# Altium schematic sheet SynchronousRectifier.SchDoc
size A; SheetNumber: 1; SheetTotal: 1
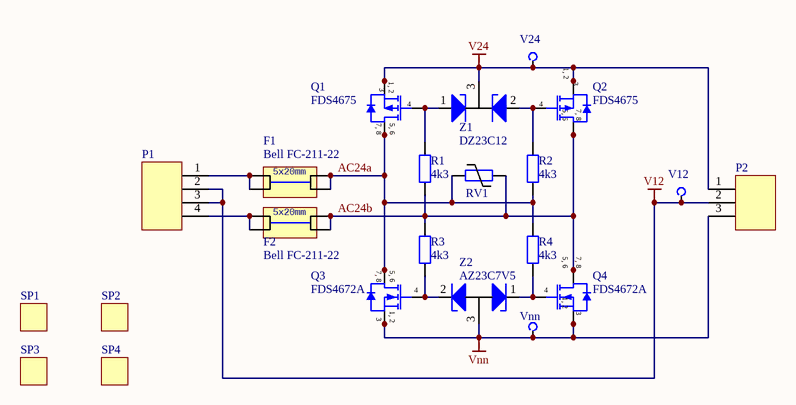
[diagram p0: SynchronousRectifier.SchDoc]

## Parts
F1  Bell FC-211-22  [FUSE_CLIP_5x20]
F2  Bell FC-211-22  [FUSE_CLIP_5x20]
P1  Terminal4_5.08mm  [MOLEX-39544-3004]  (value not drawn)
P2  Terminal3_5.08mm  [MOLEX-39544-3003]  (value not drawn)
Q1  FDS4675  [SO-8_M]
Q2  FDS4675  [SO-8_M]
Q3  FDS4672A  [SO-8_M]
Q4  FDS4672A  [SO-8_M]
R1  4k3  [CR1608-0603_N]
R2  4k3  [CR1608-0603_N]
R3  4k3  [CR1608-0603_N]
R4  4k3  [CR1608-0603_N]
RV1  V33MLA1206NHAUTO  [VR3216-1206]  (value not drawn)
SP1  Spacer-3mm-tapped x 10mm  [Spacer-3mm tapped x 10 mm]  (value not drawn)
SP2  Spacer-3mm-tapped x 10mm  [Spacer-3mm tapped x 10 mm]  (value not drawn)
SP3  Spacer-3mm-tapped x 10mm  [Spacer-3mm tapped x 10 mm]  (value not drawn)
SP4  Spacer-3mm-tapped x 10mm  [Spacer-3mm tapped x 10 mm]  (value not drawn)
V12  Power 12V FWR  [PCBPIN - 0.7mm]  (value not drawn)  (no BOM)
V24  Power 24V FWR  [PCBPIN - 0.7mm]  (value not drawn)  (no BOM)
Vnn  Power Ground  [PCBPIN - 0.7mm]  (value not drawn)  (no BOM)
Z1  DZ23C12  [SOT23_M]
Z2  AZ23C7V5  [SOT23_M]

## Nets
V12: P1.2 P1.3 P2.2 V12.1(TP)
V24: P2.1 Q1.1(S) Q1.2(S) Q1.3(S) Q2.1(S) Q2.2(S) Q2.3(S) V24.1(TP) Z1.3(K)
Vnn: P2.3 Q3.1(S) Q3.2(S) Q3.3(S) Q4.1(S) Q4.2(S) Q4.3(S) Vnn.1(TP) Z2.3(K)
AC24a: F1.2 F1.2a Q1.5(D) Q1.6(D) Q1.7(D) Q1.8(D) Q3.5(D) Q3.6(D) Q3.7(D) Q3.8(D) R2.1 R4.2 RV1.2
AC24b: F2.2 F2.2a Q2.5(D) Q2.6(D) Q2.7(D) Q2.8(D) Q4.5(D) Q4.6(D) Q4.7(D) Q4.8(D) R1.1 R3.2 RV1.1
NetF1_1: F1.1 F1.1a P1.1
NetF2_1: F2.1 F2.1a P1.4
NetQ1_4: Q1.4(G) R1.2 Z1.1(A1)
NetQ2_4: Q2.4(G) R2.2 Z1.2(A2)
NetQ3_4: Q3.4(G) R3.1 Z2.2(A2)
NetQ4_4: Q4.4(G) R4.1 Z2.1(A1)

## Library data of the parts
F1 F2 = FUSE_CLIP_5x20: 5x20mm fuse clip PCB Mount; Value: 10 A
P1 = Terminal4_5.08mm: MULTICOMP MC24368 TERMINAL BLOCK EUROSTYLE, 4 POSITION, 26-12AWG, 5.08mm
P2 = Terminal3_5.08mm: MULTICOMP MC24367 TERMINAL BLOCK EUROSTYLE, 3 POSITION, 26-12AWG, 5.08mm
Q1 Q2 = FDS4675: P-Channel Power MOSFET, 11 A, 40 V, RDS(ON) = 0.013 ohm @ VGS = -10   VRDS(ON) = 0.017 ohm @ VGS =   -4.5 VC; Manufacturer: Fairchild Semiconductor; Package Version: Rev. 16, 08/2015; Qg Gate Charge: 56nC; Drain-to-Source Voltage [Vdss]: 40V; Drain-Source On Resistance-Max: 13mO; Rated Power Dissipation: 2.4W
Q3 Q4 = FDS4672A: N-Channel Power MOSFET, 11 A, 40 V. RDS(ON)  = .013 ohm @ VGS = 4.5 V; Manufacturer: Fairchild Semiconductor; Package Version: Rev. 16, 08/2015; Channel Type: P-Channel; Qg Gate Charge: 56nC; Drain-to-Source Voltage [Vdss]: 40V; Drain-Source On Resistance-Max: 13mO; Rated Power Dissipation: 2.4W
R1-R4 = Res_CR0603: Resistor SMT 0603; Manufacturer: Generic Components; Class: Passive
RV1 = V33MLA1206NHAUTO: V33MLA1206NH - TVS Varistor, 26 V, 33 V, MLA Series, 75 V, 1206 [3216 Metric], Multilayer Varistor (MLV); Manufacturer: Generic Components; Class: Passive; SubClass: Resistor
SP1-SP4 = Spacer-3mm-tapped x 10mm: 6MM Spacer
V12 V24 Vnn = TP: Test Point
Z1 = DZ23Cxx: Dual silicon planar Zener diodes
Z2 = AZ23Cxx: Dual silicon planar Zener diodes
